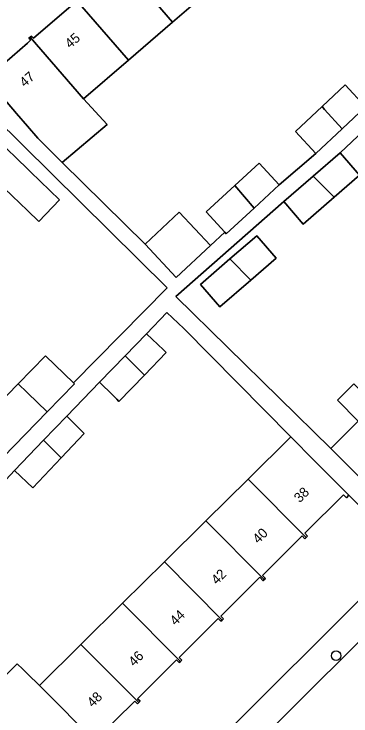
# Model space of a CAD drawing. Extents: x 159217 to 160349, y 381246 to 382172.
# Drawn here: x 159998.6 to 160033.1, y 381809.4 to 381881.2 of the extents above; entities that cross this region are included whole.
import ezdxf

# ---------------------------------------------------------------- set-up
doc = ezdxf.new("R2010")
doc.units = 0
for name, color, linetype in [('IMGEO_Boom', 7, 'Continuous'), ('IMGEO_Erf', 7, 'Continuous'), ('IMGEO_Pand', 7, 'Continuous'), ('IMGEO_Pand_nummerreeks', 7, 'Continuous'), ('IMGEO_Rijbaan_lokaal_open', 7, 'Continuous'), ('IMGEO_Voetpad_open', 7, 'Continuous')]:
    doc.layers.add(name, color=color, linetype=linetype)

msp = doc.modelspace()

# ---------------------------------------------------------------- linework, layer by layer
at = {"layer": 'IMGEO_Boom'}
msp.add_circle((160031.592, 381815.572), 0.489, dxfattribs=at)
at = {"layer": 'IMGEO_Erf'}
for points in [[(160000, 381884.944), (159992.495, 381878.483), (159995.622, 381874.85), (159995.866, 381875.061), (159996.048, 381874.849), (160000, 381878.25), (160000.352, 381878.567), (160000.162, 381878.746), (160000.287, 381878.853), (160000.413, 381878.962), (160000.606, 381878.737), (160004.954, 381882.478)], [(160019.398, 381884.3), (160014.863, 381880.397), (160010.339, 381876.502), (160005.743, 381872.547), (160008.172, 381869.927), (160003.554, 381866.049), (160012.039, 381857.676), (160015.539, 381860.959), (160018.739, 381857.548), (160020.198, 381858.889), (160018.281, 381860.974), (160021.227, 381863.682), (160023.718, 381865.973), (160025.775, 381863.736), (160029.518, 381866.969), (160027.425, 381869.205), (160030.153, 381871.758), (160032.517, 381873.969), (160034.609, 381871.732)], [(160035.023, 381869.86), (160031.999, 381867.015), (160033.983, 381864.724), (160031.392, 381862.479), (160028.223, 381859.735), (160026.239, 381862.026), (160015.199, 381852.34), (160031.057, 381836.782), (160033.85, 381839.56), (160031.717, 381841.714), (160033.388, 381843.375)], [(159996.728, 381868.533), (160000, 381865.377), (160000.327, 381865.062), (160003.3, 381862.225), (160001.156, 381860.003), (160000, 381861.114), (159997.646, 381863.377)], [(159994.679, 381810.489), (159998.958, 381814.756), (159999.533, 381814.18), (160000, 381813.721), (160001.226, 381812.517), (160005.473, 381816.718), (160009.745, 381820.942), (160014.013, 381825.164), (160018.256, 381829.361), (160022.586, 381833.644), (160026.948, 381837.958), (160015.992, 381849.038), (160014.258, 381850.683), (160012.171, 381848.519), (160013.924, 381846.857), (160014.201, 381846.593), (160011.975, 381844.285), (160009.37, 381841.582), (160009.14, 381841.812), (160008.734, 381842.22), (160007.393, 381843.564), (160004.036, 381840.082), (160005.811, 381838.302), (160003.449, 381835.811), (160000.544, 381832.748), (159998.686, 381834.511), (159995.596, 381831.255)], [(160038.791, 381826.068), (160032.904, 381831.986), (160032.649, 381831.732), (160032.341, 381832.042), (160028.382, 381828.094), (160028.668, 381827.808), (160028.536, 381827.677), (160028.402, 381827.543), (160028.111, 381827.835), (160024.051, 381823.786), (160024.352, 381823.484), (160024.234, 381823.366), (160024.117, 381823.249), (160023.771, 381823.596), (160019.794, 381819.63), (160020.067, 381819.356), (160019.992, 381819.281), (160019.921, 381819.21), (160019.804, 381819.093), (160019.518, 381819.38), (160015.531, 381815.403), (160015.803, 381815.129), (160015.665, 381814.991), (160015.541, 381814.867), (160015.265, 381815.143), (160011.277, 381811.166), (160011.536, 381810.907), (160011.401, 381810.773), (160011.27, 381810.642), (160010.979, 381810.935), (160007.018, 381806.985)], [(160000.048, 381787.508), (160008.419, 381795.853), (160038.791, 381826.068)]]:
    msp.add_lwpolyline(points, dxfattribs=at)
for points in [[(159994.561, 381838.781), (159999.055, 381843.386), (160001.857, 381846.257), (160004.708, 381843.475), (160014.315, 381853.212), (159990.64, 381876.569), (159957.007, 381841.635), (159955.642, 381840.217), (159958.818, 381836.919), (159957.077, 381834.899), (159952.057, 381829.709), (159972.505, 381809.81), (159974.918, 381812.289), (159970.479, 381816.617), (159974.953, 381821.209), (159979.393, 381816.882), (159984.048, 381822.097), (159980.266, 381818.215), (159978.214, 381820.214), (159981.998, 381824.097), (159981.093, 381824.98), (159985.545, 381829.543), (159990.058, 381834.167)], [(160025.459, 381856.248), (160022.866, 381854.002), (160019.699, 381851.259), (160017.715, 381853.55), (160020.729, 381856.161), (160023.475, 381858.539)]]:
    msp.add_lwpolyline(points, close=True, dxfattribs=at)
at = {"layer": 'IMGEO_Pand'}
for points in [[(160013.927, 381890.622), (160013.787, 381890.502), (160013.99, 381890.266), (160009.726, 381886.595), (160009.521, 381886.832), (160009.392, 381886.721), (160014.863, 381880.397), (160019.398, 381884.3)], [(160010.339, 381876.502), (160014.863, 381880.397), (160009.392, 381886.721), (160009.266, 381886.612), (160009.466, 381886.38), (160005.191, 381882.7), (160005.012, 381882.908), (160004.889, 381882.802)], [(160005.743, 381872.547), (160010.339, 381876.502), (160004.889, 381882.802), (160004.766, 381882.696), (160004.954, 381882.478), (160000.606, 381878.737), (160000.413, 381878.962), (160000.287, 381878.853)], [(160000.287, 381878.853), (160000.162, 381878.746), (160000.352, 381878.567), (160000, 381878.25), (159996.048, 381874.849), (159995.866, 381875.061), (159995.622, 381874.85), (159998.884, 381871.061), (160000, 381869.752), (160001.057, 381868.513), (160003.554, 381866.049), (160008.172, 381869.927), (160005.743, 381872.547)], [(160030.153, 381871.758), (160030.398, 381871.472), (160032.202, 381869.48), (160034.609, 381871.732), (160032.517, 381873.969)], [(160030.153, 381871.758), (160027.425, 381869.205), (160029.518, 381866.969), (160032.202, 381869.48), (160030.398, 381871.472)], [(159986.21, 381865.178), (159993.381, 381858.244), (159993.489, 381858.137), (159995.286, 381860), (159994.82, 381860.449), (159997.646, 381863.377), (160000, 381861.114), (160001.156, 381860.003), (160003.3, 381862.225), (160000.327, 381865.062), (160000, 381865.377), (159996.728, 381868.533), (159994.697, 381866.428), (159991.186, 381869.815), (159990.977, 381870.016), (159990.762, 381869.806), (159990.936, 381869.646), (159986.559, 381865.109), (159986.344, 381865.317)], [(160031.392, 381862.479), (160033.983, 381864.724), (160031.999, 381867.015), (160029.255, 381864.638)], [(160021.227, 381863.682), (160023.195, 381861.365), (160025.775, 381863.736), (160023.718, 381865.973)], [(160031.392, 381862.479), (160029.255, 381864.638), (160026.239, 381862.026), (160028.223, 381859.735)], [(160023.195, 381861.365), (160021.227, 381863.682), (160018.281, 381860.974), (160020.198, 381858.889), (160020.337, 381858.737)], [(160018.739, 381857.548), (160015.539, 381860.959), (160012.039, 381857.676), (160015.239, 381854.265)], [(160022.866, 381854.002), (160025.459, 381856.248), (160023.475, 381858.539), (160020.729, 381856.161)], [(160022.866, 381854.002), (160020.729, 381856.161), (160017.715, 381853.55), (160019.699, 381851.259)], [(160009.999, 381846.267), (160011.724, 381844.537), (160011.975, 381844.285), (160014.201, 381846.593), (160013.924, 381846.857), (160012.171, 381848.519)], [(160004.708, 381843.475), (160001.857, 381846.257), (159999.055, 381843.386), (159999.976, 381842.488), (160000, 381842.465), (160002.027, 381840.519), (160004.812, 381843.373)], [(160011.975, 381844.285), (160011.724, 381844.537), (160009.999, 381846.267), (160007.393, 381843.564), (160008.734, 381842.22), (160009.14, 381841.812), (160009.37, 381841.582)], [(159994.561, 381838.781), (159995.539, 381837.867), (159997.552, 381835.934), (160002.027, 381840.519), (160000, 381842.465), (159999.976, 381842.488), (159999.055, 381843.386)], [(160041.453, 381835.23), (160035.521, 381841.221), (160033.388, 381843.375), (160031.717, 381841.714), (160033.85, 381839.56), (160031.057, 381836.782), (160033.461, 381834.364), (160036.986, 381830.818), (160037.256, 381831.086), (160037.025, 381831.319), (160041.084, 381835.356), (160041.33, 381835.108)], [(160004.036, 381840.082), (160001.658, 381837.615), (160003.449, 381835.811), (160005.811, 381838.302)], [(160003.449, 381835.811), (160001.658, 381837.615), (159998.686, 381834.511), (160000.544, 381832.748)], [(160028.536, 381827.677), (160028.668, 381827.808), (160028.382, 381828.094), (160032.341, 381832.042), (160032.649, 381831.732), (160032.904, 381831.986), (160029.373, 381835.526), (160026.948, 381837.958), (160022.586, 381833.644)], [(160028.536, 381827.677), (160022.586, 381833.644), (160018.256, 381829.361), (160024.234, 381823.366), (160024.352, 381823.484), (160024.051, 381823.786), (160028.111, 381827.835), (160028.402, 381827.543)], [(160014.013, 381825.164), (160019.921, 381819.21), (160019.992, 381819.281), (160020.067, 381819.356), (160019.794, 381819.63), (160023.771, 381823.596), (160024.117, 381823.249), (160024.234, 381823.366), (160018.256, 381829.361)], [(160015.665, 381814.991), (160015.803, 381815.129), (160015.531, 381815.403), (160019.518, 381819.38), (160019.804, 381819.093), (160019.921, 381819.21), (160014.013, 381825.164), (160009.745, 381820.942)], [(160015.665, 381814.991), (160009.745, 381820.942), (160005.473, 381816.718), (160011.401, 381810.773), (160011.536, 381810.907), (160011.277, 381811.166), (160015.265, 381815.143), (160015.541, 381814.867)], [(160011.401, 381810.773), (160005.473, 381816.718), (160001.226, 381812.517), (160007.163, 381806.547), (160007.234, 381806.618), (160007.309, 381806.693), (160007.018, 381806.985), (160010.979, 381810.935), (160011.27, 381810.642)], [(160007.163, 381806.547), (160001.226, 381812.517), (160000, 381813.721), (159999.533, 381814.18), (159998.958, 381814.756), (159994.679, 381810.489), (159996.907, 381808.288), (160000, 381805.186), (160002.813, 381802.35), (160002.944, 381802.481), (160002.694, 381802.732), (160006.708, 381806.736), (160007.029, 381806.413)]]:
    msp.add_lwpolyline(points, close=True, dxfattribs=at)
at = {"layer": 'IMGEO_Rijbaan_lokaal_open'}
msp.add_lwpolyline([(160116.933, 381899.648), (160012.11, 381795.292), (160002.99, 381786.2), (160007.94, 381781.256), (160010.858, 381784.097), (160016.183, 381789.42), (160020.046, 381793.267), (160022.766, 381795.885), (160032.195, 381805.263), (160036.822, 381809.873), (160048.168, 381821.179), (160052.791, 381825.786), (160064.536, 381837.45), (160069.21, 381842.087), (160070.584, 381843.451), (160080.535, 381853.35), (160085.354, 381858.143), (160096.927, 381869.656), (160106.101, 381878.782), (160116.227, 381888.855)], dxfattribs=at)
at = {"layer": 'IMGEO_Voetpad_open'}
for points in [[(160135.68, 381926.914), (160133.311, 381923.988), (160130.31, 381920.165), (160122.078, 381909.579), (160119.067, 381906.332), (160118.056, 381905.241), (160114.243, 381901.129), (160079.939, 381867.002), (160078.853, 381865.922), (160078.852, 381865.921), (160040.259, 381827.528), (160038.791, 381826.068), (160008.419, 381795.853), (160000.048, 381787.508)], [(160000.461, 381783.668), (160002.99, 381786.2), (160012.11, 381795.292), (160116.933, 381899.648)], [(160045.482, 381881.556), (160043.83, 381880.035), (160041.167, 381877.583), (160036.933, 381873.686), (160034.609, 381871.732), (160032.202, 381869.48), (160029.518, 381866.969), (160025.775, 381863.736), (160023.195, 381861.365), (160020.337, 381858.737), (160020.198, 381858.889), (160018.739, 381857.548), (160015.239, 381854.265), (160012.039, 381857.676), (160003.554, 381866.049), (160001.057, 381868.513), (160000, 381869.752), (159998.884, 381871.061), (159995.622, 381874.85)], [(159990.64, 381876.569), (160014.315, 381853.212), (160004.708, 381843.475), (160004.812, 381843.373), (160002.027, 381840.519), (159997.552, 381835.934)], [(160033.461, 381834.364), (160031.057, 381836.782), (160015.199, 381852.34), (160026.239, 381862.026), (160029.255, 381864.638), (160031.999, 381867.015), (160035.023, 381869.86)], [(159995.596, 381831.255), (159998.686, 381834.511), (160001.658, 381837.615), (160004.036, 381840.082), (160007.393, 381843.564), (160009.999, 381846.267), (160012.171, 381848.519), (160014.258, 381850.683), (160015.992, 381849.038), (160026.948, 381837.958), (160029.373, 381835.526), (160032.904, 381831.986), (160038.791, 381826.068)]]:
    msp.add_lwpolyline(points, dxfattribs=at)

# ---------------------------------------------------------------- texts
at = {"layer": 'IMGEO_Pand_nummerreeks'}
for s, rotation, p in [('45', 40.79992, (160004.368, 381877.651)), ('47', 40.82324, (159999.72, 381873.686)), ('38', 44.6725, (160027.867, 381831.162)), ('40', 44.6725, (160023.631, 381826.975)), ('42', 44.6725, (160019.391, 381822.783)), ('44', 44.6725, (160015.158, 381818.598)), ('46', 44.6725, (160010.922, 381814.411)), ('48', 44.6725, (160006.69, 381810.226))]:
    msp.add_text(s, height=1, rotation=rotation, dxfattribs=at).set_placement(p)

doc.saveas('drawing.dxf')
